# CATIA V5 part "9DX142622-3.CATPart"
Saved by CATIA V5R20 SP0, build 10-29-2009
Part number: 9DX142622-3
Revision: ANY
Definition: UNKNOWN
Nomenclature: 9DX142622-3
Source: Unknown
Bounding box of the stored display mesh (mm): x -12.482 to 12.482, y 0 to 26, z -12.675 to 12.675
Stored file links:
  C:\Users\Utente\Desktop\IO LAVORO\3D X SITO CF\CUMSA\3D files DX\DX 142622\9DX142622-3.CATPart
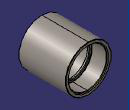
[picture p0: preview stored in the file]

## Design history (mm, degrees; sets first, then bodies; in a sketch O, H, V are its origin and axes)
Body1 "Revolución1" (main body)
  Solid1: solid without history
